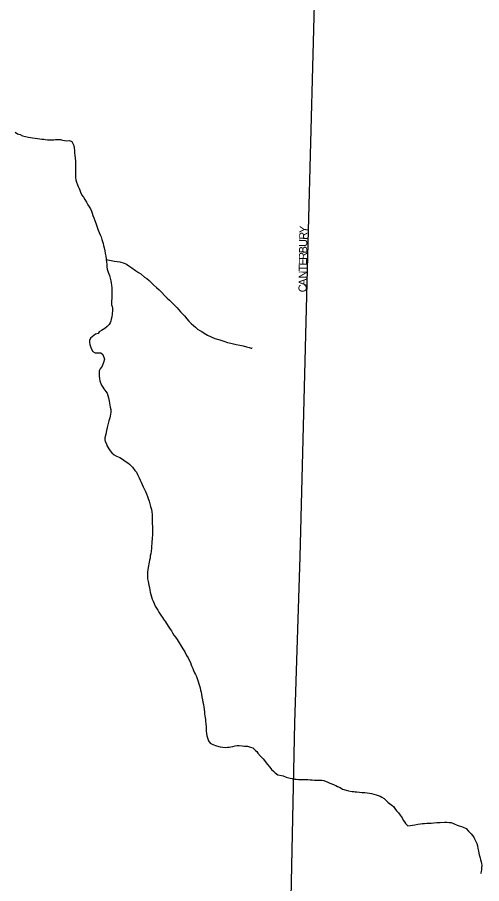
# Model space of a CAD drawing. Extents: x 2010165 to 2382125, y 1060529 to 1407316.
# Drawn here: x 2127835 to 2130672, y 1251560 to 1256857 of the extents above; entities that cross this region are included whole.
import ezdxf

# ---------------------------------------------------------------- set-up
doc = ezdxf.new("R2010")
doc.units = 0
for name, color, linetype in [('GM_X_City_Street', 7, 'Continuous'), ('GM_X_City_Street_Text', 7, 'Continuous'), ('GM_X_Minor_River', 7, 'Continuous')]:
    doc.layers.add(name, color=color, linetype=linetype)

msp = doc.modelspace()

# ---------------------------------------------------------------- linework, layer by layer
at = {"layer": 'GM_X_City_Street'}
msp.add_lwpolyline([(2129505.7, 1251348.4), (2129506.2, 1251375.3), (2129531.2, 1252543), (2129562.3, 1253559.1), (2129614.5, 1255553.3), (2129657.1, 1257170.7), (2129695.6, 1258362.1), (2129753.6, 1261212.8), (2129847.8, 1264241.5)], dxfattribs=at)
at = {"layer": 'GM_X_Minor_River'}
for points in [[(2127820.9, 1256156), (2127834.9, 1256146), (2127851, 1256140.1), (2127867.1, 1256132.1), (2127885.2, 1256128.1), (2127903.3, 1256124.2), (2127915.3, 1256122.2), (2127927.3, 1256120.2), (2127943.4, 1256118.3), (2127957.5, 1256116.3), (2127971.5, 1256114.4), (2127983.6, 1256112.4), (2127995.6, 1256112.4), (2128005.6, 1256110.4), (2128019.7, 1256108.5), (2128031.7, 1256108.5), (2128041.8, 1256108.6), (2128057.8, 1256108.6), (2128067.9, 1256110.6), (2128081.9, 1256110.7), (2128097.9, 1256110.8), (2128110, 1256106.8), (2128122, 1256104.8), (2128138.1, 1256102.8), (2128154.2, 1256104.9), (2128168.2, 1256098.9), (2128174.3, 1256086.9), (2128180.4, 1256072.9)], [(2128180.4, 1256072.9), (2128182.4, 1256058.8), (2128184.5, 1256042.8), (2128184.5, 1256026.7), (2128186.6, 1256014.7), (2128188.6, 1255996.6), (2128190.7, 1255978.6), (2128190.8, 1255962.5), (2128190.8, 1255946.5), (2128190.9, 1255928.4), (2128189.1, 1255876.2), (2128193.1, 1255864.2), (2128195.2, 1255850.2), (2128203.3, 1255834.1), (2128207.3, 1255822.1), (2128213.4, 1255810.1), (2128217.4, 1255800.1), (2128221.5, 1255788.1), (2128229.6, 1255770), (2128239.7, 1255758), (2128247.7, 1255744), (2128257.8, 1255728), (2128265.9, 1255711.9), (2128274, 1255697.9), (2128282, 1255685.9), (2128288.1, 1255671.9), (2128292.2, 1255659.8), (2128296.2, 1255645.8), (2128302.3, 1255631.8), (2128308.4, 1255615.8), (2128316.5, 1255591.7), (2128322.6, 1255573.6), (2128328.7, 1255555.6), (2128334.7, 1255541.6), (2128340.8, 1255527.6), (2128346.9, 1255515.5), (2128350.9, 1255499.5), (2128355, 1255487.5), (2128359, 1255475.4), (2128361.1, 1255461.4), (2128365.2, 1255447.3), (2128369.2, 1255429.3), (2128371.3, 1255413.2), (2128375.4, 1255397.2), (2128377.4, 1255379.2), (2128379.5, 1255361.1), (2128381.6, 1255347.1), (2128381.6, 1255331), (2128383.7, 1255317), (2128389.8, 1255298.9), (2128393.8, 1255288.9), (2128397.9, 1255278.9), (2128401.9, 1255262.8), (2128406, 1255246.8), (2128408.1, 1255232.8), (2128410.1, 1255218.7), (2128412.2, 1255202.7), (2128412.2, 1255186.6), (2128412.4, 1255142.5), (2128410.5, 1255120.4), (2128410.5, 1255100.3), (2128414.6, 1255088.3), (2128416.6, 1255078.3), (2128416.7, 1255066.2), (2128414.8, 1255042.1), (2128412.8, 1255026.1), (2128408.8, 1255012), (2128406.9, 1255000), (2128400.9, 1254989.9), (2128394.9, 1254979.9), (2128382.9, 1254967.8), (2128368.9, 1254955.7), (2128348.9, 1254941.6), (2128334.9, 1254933.5), (2128328.9, 1254923.5), (2128312.9, 1254919.4), (2128292.8, 1254903.3), (2128280.8, 1254895.2), (2128274.9, 1254881.1), (2128274.9, 1254869.1), (2128276.9, 1254857.1), (2128281, 1254845), (2128287.1, 1254829), (2128295.2, 1254815), (2128311.2, 1254805), (2128321.3, 1254805), (2128333.3, 1254805.1), (2128345.4, 1254805.1), (2128357.4, 1254795.1), (2128367.6, 1254767.1), (2128361.6, 1254747), (2128353.7, 1254724.9), (2128341.7, 1254708.8), (2128333.7, 1254696.7), (2128333.8, 1254676.6), (2128333.8, 1254664.6), (2128335.9, 1254646.5), (2128337.9, 1254634.5), (2128344, 1254618.5), (2128348.1, 1254608.4), (2128356.1, 1254596.4)], [(2128377.8, 1255375.8), (2128427.7, 1255367.3), (2128461.8, 1255361.4), (2128487.9, 1255353.4), (2128502, 1255347.4), (2128516.1, 1255337.5), (2128534.1, 1255325.5), (2128556.3, 1255309.5), (2128574.4, 1255297.5), (2128588.5, 1255289.5), (2128612.6, 1255269.5), (2128626.7, 1255259.5), (2128640.8, 1255247.6), (2128652.9, 1255235.6), (2128667, 1255221.5), (2128685.1, 1255205.6), (2128701.2, 1255191.5), (2128749.5, 1255139.5), (2128763.6, 1255127.5), (2128777.7, 1255115.5), (2128789.8, 1255103.5), (2128801.9, 1255091.5), (2128811.9, 1255081.5), (2128822, 1255069.5), (2128832.1, 1255057.5), (2128844.2, 1255043.5), (2128856.3, 1255031.5), (2128870.4, 1255013.5), (2128882.5, 1254999.5), (2128896.6, 1254985.5), (2128910.6, 1254973.5), (2128922.7, 1254963.5), (2128934.8, 1254951.5), (2128948.9, 1254941.5), (2128962.9, 1254935.5), (2128977, 1254925.5), (2128997.1, 1254913.5), (2129019.3, 1254903.6), (2129041.4, 1254893.6), (2129071.5, 1254885.7), (2129095.6, 1254877.7), (2129119.7, 1254869.8), (2129139.8, 1254865.8), (2129155.8, 1254861.9), (2129171.9, 1254855.9), (2129194, 1254852), (2129214.1, 1254848), (2129234.2, 1254842.1), (2129252.3, 1254838.1), (2129264.3, 1254834.1), (2129268.3, 1254834.1), (2129270.3, 1254838.1)], [(2128356.1, 1254596.4), (2128364.2, 1254586.4), (2128376.3, 1254570.4), (2128384.4, 1254558.4), (2128388.4, 1254544.4), (2128392.5, 1254530.3), (2128394.5, 1254520.3), (2128396.6, 1254510.3), (2128398.6, 1254498.2), (2128400.7, 1254486.2), (2128402.7, 1254474.2), (2128406.8, 1254460.1), (2128406.8, 1254444.1), (2128404.9, 1254430), (2128402.9, 1254418), (2128398.9, 1254407.9), (2128393, 1254389.8), (2128383.1, 1254349.7), (2128379.1, 1254331.6), (2128375.2, 1254309.5), (2128369.3, 1254285.4), (2128369.3, 1254273.4), (2128371.4, 1254263.3), (2128379.4, 1254249.3), (2128381.5, 1254239.3), (2128387.5, 1254229.3), (2128393.6, 1254219.3), (2128401.7, 1254207.2), (2128411.7, 1254195.2), (2128425.8, 1254183.2), (2128439.9, 1254173.3), (2128460, 1254165.3), (2128478.1, 1254155.3), (2128494.2, 1254143.3), (2128510.3, 1254133.3), (2128520.3, 1254125.3), (2128538.5, 1254107.3), (2128552.6, 1254087.3), (2128562.6, 1254075.3), (2128568.7, 1254061.3), (2128578.8, 1254041.3), (2128584.9, 1254027.2), (2128591, 1254015.2), (2128597, 1254001.2), (2128603.1, 1253987.1), (2128611.2, 1253971.1), (2128617.3, 1253957.1), (2128623.3, 1253943.1), (2128629.4, 1253927), (2128635.5, 1253909), (2128639.5, 1253899), (2128643.6, 1253882.9), (2128647.7, 1253866.9), (2128653.7, 1253848.8), (2128655.8, 1253832.8), (2128657.9, 1253816.7), (2128657.9, 1253798.7), (2128658, 1253780.6), (2128658, 1253768.6), (2128658.1, 1253758.5), (2128660.1, 1253748.5), (2128660.2, 1253732.5), (2128660.2, 1253718.4), (2128660.3, 1253698.3), (2128658.4, 1253666.2), (2128656.5, 1253652.2), (2128656.5, 1253638.1), (2128654.5, 1253626.1), (2128654.6, 1253610), (2128652.6, 1253594), (2128650.7, 1253577.9), (2128646.7, 1253563.8), (2128646.8, 1253549.8), (2128642.8, 1253537.7), (2128640.9, 1253525.7), (2128638.9, 1253515.6), (2128636.9, 1253503.6), (2128634.9, 1253493.6), (2128633, 1253479.5), (2128631, 1253467.5), (2128629.1, 1253455.4), (2128629.1, 1253445.4), (2128629.2, 1253423.3), (2128633.2, 1253407.3), (2128637.3, 1253385.2), (2128641.4, 1253371.2), (2128643.5, 1253355.1), (2128645.5, 1253343.1), (2128649.6, 1253329), (2128653.6, 1253313), (2128657.7, 1253299), (2128663.8, 1253286.9), (2128669.8, 1253272.9), (2128675.9, 1253256.9), (2128686, 1253244.9), (2128694.1, 1253232.9), (2128700.1, 1253220.8), (2128708.2, 1253208.8), (2128716.3, 1253196.8), (2128722.3, 1253186.8), (2128728.4, 1253176.8)], [(2128728.4, 1253176.8), (2128740.5, 1253160.8), (2128746.5, 1253150.7), (2128760.6, 1253128.7), (2128768.7, 1253116.7), (2128776.8, 1253106.7), (2128782.8, 1253094.7), (2128790.9, 1253080.6), (2128801, 1253066.6), (2128811.1, 1253052.6), (2128845.4, 1252996.5), (2128857.5, 1252978.5), (2128867.6, 1252954.5), (2128877.7, 1252940.4), (2128883.8, 1252926.4), (2128891.9, 1252912.4), (2128897.9, 1252898.4), (2128902, 1252888.3), (2128908, 1252876.3), (2128912.1, 1252864.3), (2128918.2, 1252850.3), (2128924.2, 1252838.2), (2128930.3, 1252826.2), (2128934.3, 1252814.2), (2128940.4, 1252796.1), (2128944.5, 1252782.1), (2128948.5, 1252770.1), (2128952.6, 1252758.1), (2128954.7, 1252744), (2128958.7, 1252732), (2128960.8, 1252715.9), (2128962.8, 1252701.9), (2128966.9, 1252683.8), (2128969, 1252669.8), (2128973, 1252655.8), (2128975.1, 1252639.7), (2128977.1, 1252625.7), (2128979.2, 1252611.6), (2128979.2, 1252599.6), (2128981.3, 1252585.6), (2128983.3, 1252573.5), (2128985.4, 1252563.5), (2128985.4, 1252553.5), (2128987.5, 1252537.4), (2128987.6, 1252519.4), (2128987.6, 1252505.3), (2128987.6, 1252493.3), (2128989.7, 1252479.2), (2128991.8, 1252463.2), (2128997.8, 1252445.1), (2129001.9, 1252433.1), (2129014, 1252419.1), (2129030.1, 1252411.1), (2129052.2, 1252403.2), (2129074.3, 1252397.2), (2129090.3, 1252395.2), (2129104.4, 1252393.3), (2129118.4, 1252395.3), (2129128.5, 1252395.4), (2129138.5, 1252397.4), (2129152.5, 1252399.5), (2129166.6, 1252403.5), (2129178.6, 1252405.6), (2129190.6, 1252405.6), (2129208.7, 1252403.7), (2129222.8, 1252401.7), (2129240.8, 1252401.8), (2129258.9, 1252395.8), (2129273, 1252389.8), (2129289.1, 1252373.8), (2129299.1, 1252367.8), (2129305.2, 1252357.8), (2129321.3, 1252339.8), (2129337.4, 1252323.8), (2129363.6, 1252289.8), (2129377.7, 1252271.7), (2129387.8, 1252257.7), (2129399.9, 1252247.7), (2129410, 1252237.7), (2129426.1, 1252225.7), (2129448.1, 1252221.8), (2129458.2, 1252219.8), (2129478.3, 1252211.8), (2129502.4, 1252205.9), (2129514.4, 1252203.9), (2129528.5, 1252200), (2129538.5, 1252200), (2129552.6, 1252198), (2129562.6, 1252198.1), (2129572.6, 1252198.1), (2129586.7, 1252196.1), (2129600.7, 1252196.2), (2129610.8, 1252196.2), (2129624.8, 1252194.3), (2129636.9, 1252194.3), (2129650.9, 1252192.3), (2129665, 1252192.4), (2129675, 1252192.4), (2129685, 1252192.4), (2129695.1, 1252192.5), (2129707.1, 1252190.5)], [(2129707.1, 1252190.5), (2129731.2, 1252180.6), (2129743.3, 1252174.6), (2129757.3, 1252170.6), (2129771.4, 1252164.6), (2129781.5, 1252160.6), (2129791.5, 1252154.6), (2129807.6, 1252148.7), (2129821.7, 1252138.7), (2129843.8, 1252132.7), (2129857.8, 1252126.8), (2129879.9, 1252122.8), (2129890, 1252122.8), (2129900, 1252120.9), (2129910, 1252120.9), (2129926.1, 1252118.9), (2129940.1, 1252117), (2129958.2, 1252117.1), (2129972.3, 1252115.1), (2129986.3, 1252113.1), (2129998.4, 1252111.2), (2130012.4, 1252107.2), (2130026.5, 1252103.2), (2130040.5, 1252099.2), (2130052.6, 1252095.3), (2130062.7, 1252089.3), (2130076.7, 1252081.3), (2130086.8, 1252071.3), (2130098.9, 1252059.3), (2130111, 1252049.3), (2130121, 1252041.3), (2130135.1, 1252029.3), (2130141.2, 1252019.3), (2130151.2, 1252005.3), (2130163.3, 1251993.3), (2130173.4, 1251979.3), (2130185.5, 1251963.2), (2130191.6, 1251949.2), (2130199.6, 1251939.2), (2130207.7, 1251927.2), (2130221.8, 1251913.2), (2130235.8, 1251915.2), (2130263.9, 1251919.3), (2130282, 1251923.4), (2130298, 1251925.5), (2130310, 1251927.5), (2130322.1, 1251927.6), (2130338.1, 1251929.6), (2130352.2, 1251929.6), (2130364.2, 1251929.7), (2130380.3, 1251931.8), (2130398.3, 1251933.8), (2130418.4, 1251933.9), (2130444.5, 1251936), (2130458.5, 1251936), (2130472.6, 1251934.1), (2130486.6, 1251934.1), (2130504.7, 1251926.1), (2130522.8, 1251918.2), (2130534.8, 1251914.2), (2130548.9, 1251910.2), (2130558.9, 1251906.2), (2130577, 1251898.3), (2130591.2, 1251880.2), (2130607.3, 1251864.2), (2130615.3, 1251854.2), (2130623.4, 1251844.2), (2130629.4, 1251834.2), (2130635.5, 1251822.2), (2130643.6, 1251806.2), (2130647.6, 1251792.1), (2130649.7, 1251776.1), (2130653.8, 1251758), (2130657.9, 1251735.9), (2130662, 1251717.9), (2130666, 1251705.9), (2130670.1, 1251693.8), (2130672.1, 1251683.8), (2130672.2, 1251671.8), (2130670.2, 1251657.7), (2130670.2, 1251645.7), (2130668.3, 1251635.6), (2130666.3, 1251623.6), (2130664.3, 1251619.6)]]:
    msp.add_lwpolyline(points, dxfattribs=at)

# ---------------------------------------------------------------- texts
at = {"layer": 'GM_X_City_Street_Text'}
for s, rotation, p in [('Y', 86.1728, (2129607.3, 1255536.1)), ('R', 89.2281, (2129606.8, 1255497.2)), ('B', 89.2228, (2129605.7, 1255413.6)), ('U', 89.2327, (2129606.2, 1255453.2)), ('R', 89.2339, (2129605.2, 1255374)), ('E', 89.2213, (2129604.7, 1255338.8)), ('N', 89.227, (2129603.6, 1255259.6)), ('T', 89.2353, (2129604.2, 1255303.6)), ('A', 89.2327, (2129603, 1255215.6)), ('C', 89.2228, (2129602.5, 1255176))]:
    msp.add_text(s, height=50, rotation=rotation, dxfattribs=at).set_placement(p)

doc.saveas('drawing.dxf')
